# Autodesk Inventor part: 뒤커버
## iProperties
Company: 한국ATC센터
Created: 2014-11
Part Number: 뒤커버
Document SubType Name: Modeling
Designer: KYOUNG IL JANG
Density: 2.71 g/cm^3
Material: 알루미늄-6061
Mass: 280.898 g
Surface Area: 198.677 cm^2
Volume: 103.653 cm^3
Author: KYOUNG IL JANG
